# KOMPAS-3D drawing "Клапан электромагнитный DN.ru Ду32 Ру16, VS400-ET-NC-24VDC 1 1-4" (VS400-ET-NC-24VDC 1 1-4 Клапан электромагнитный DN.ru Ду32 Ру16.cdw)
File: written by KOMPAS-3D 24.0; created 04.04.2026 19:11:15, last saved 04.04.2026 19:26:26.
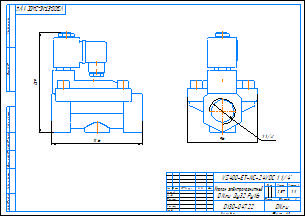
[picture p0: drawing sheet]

Document properties: c3d_UniqueCompID: ef56311e-7521-43dc-8291-0e6108b3d81d; Обозначение: VS400-ET-NC-220VAC 1; Наименование: Клапан электромагнитный DN.ru Ду25 Ру16; Автор: artio; Класс точности: c; Знак неуказанной шероховатости: Шероховатость не задана; Рассекать на разрезах: Да; c3d_UniqueCompID: ef56311e-7521-43dc-8291-0e6108b3d81d; Обозначение: VS400-ET-NC-220VAC 1-2; Наименование: Клапан электромагнитный DN.ru Ду15 Ру16; Автор: artio; Класс точности: c; Знак неуказанной шероховатости: Шероховатость не задана; Рассекать на разрезах: Да; c3d_UniqueCompID: ef56311e-7521-43dc-8291-0e6108b3d81d; Обозначение: VS400-ET-NC-220VAC 3-4; Наименование: Клапан электромагнитный DN.ru Ду20 Ру16; Автор: artio; Класс точности: c; Знак неуказанной шероховатости: Шероховатость не задана; Рассекать на разрезах: Да; c3d_UniqueCompID: ef56311e-7521-43dc-8291-0e6108b3d81d; Обозначение: VS400-ET-NC-220VAC 1 1-4; Наименование: Клапан электромагнитный DN.ru Ду32 Ру16; Автор: artio; Класс точности: c; Знак неуказанной шероховатости: Шероховатость не задана; Рассекать на разрезах: Да; c3d_UniqueCompID: ef56311e-7521-43dc-8291-0e6108b3d81d; Обозначение: VS400-ET-NC-220VAC 3-8; Наименование: Клапан электромагнитный DN.ru Ду10 Ру16; Автор: artio; Класс точности: c; Знак неуказанной шероховатости: Шероховатость не задана; Рассекать на разрезах: Да; Автор: artio; Форматы листов документа: A3; Полное имя файла: VS400-ET-NC-24VDC 1 1-4 Клапан электромагнитный DN.ru Ду32 Ру16.m3d; Масса: 2.569; Наименование: Клапан электромагнитный DN.ru Ду32 Ру16; Количество листов документа: 1; Примечание: D130-04722

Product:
- Body: Тело 1  | qty 1
    Масса: 4.144257
- Part/product: Клапан электромагнитный DN.ru Ду32 Ру16  | designation VS400-ET-NC-24VDC 1 1-4
    Масса: 2.569
    Раздел спецификации: Прочие изделия
    Примечание: D130-04722
    additional columns: ef56311e-7521-43dc-8291-0e6108b3d81d; VS400-ET-NC-220VAC 1 1-4; artio; c; Шероховатость не задана; Да

Views: Вид 1, Спереди
Referenced files in C:\Users\artio\OneDrive\Рабочий стол\Клапан электромагнитный DN.ru\VS400-ET-NC\VS400-ET-NC-24VDC\: VS400-ET-NC-24VDC 3-8 Клапан электромагнитный DN.ru Ду10 Ру16.m3d, VS400-ET-NC-24VDC 1 1-4 Клапан электромагнитный DN.ru Ду32 Ру16.m3d
Referenced files in C:\Users\artio\OneDrive\Рабочий стол\Клапан электромагнитный DN.ru\VS400-ET-NC\: VS400-ET-NC-24VDC 3-8 Клапан электромагнитный DN.ru Ду10 Ру16.cdw
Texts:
  VS400-ET-NC-24VDC 1 1-4
  Клапан электромагнитный
  DN.ru Ду32 Ру16
  VS400-ET-NC-24VDC 1 1/4"
  VS400-ET-NC-24VDC 1 1/4"-
  Клапан электромагнитный DN.ru Ду32 Ру16
  VS400-ET-NC-24VDC 1 1-4 Клапан электромагнитный DN.ru Ду32 Ру16
Dimensions and other numbers on the sheet: 0; 3; 2; 4; 96; 1 1/4"; 1:1; 1; 2,57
